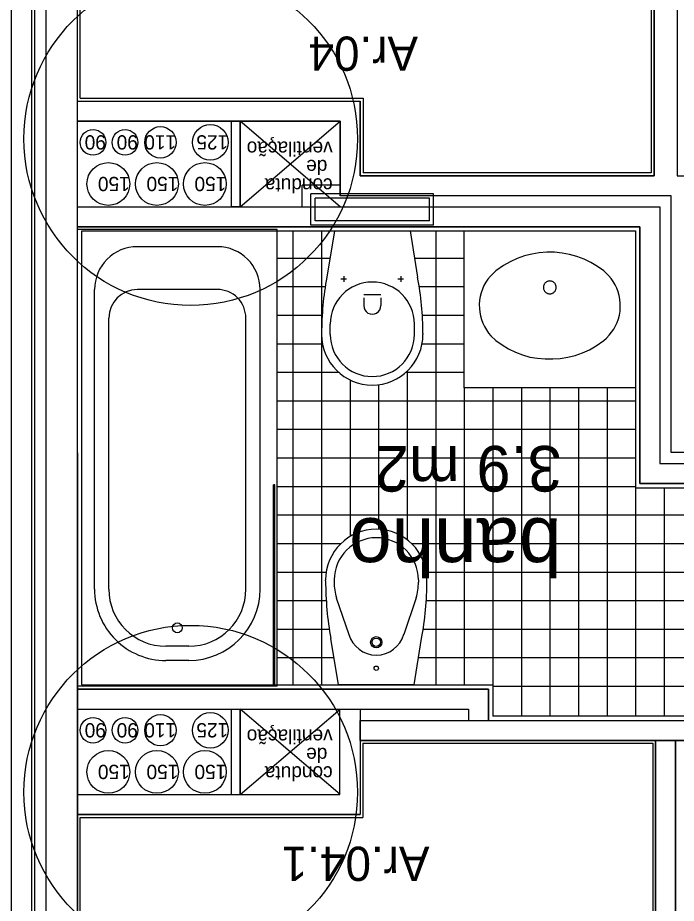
# Model space of a CAD drawing. Extents: x 1278 to 1356, y -253.7 to -224.
# Drawn here: x 1334.624 to 1336.931, y -240.985 to -237.882 of the extents above; entities that cross this region are included whole.
import ezdxf

# ---------------------------------------------------------------- set-up
doc = ezdxf.new("R2010")
doc.units = 0
for name, color, linetype in [('Level 1', 7, 'Continuous'), ('Level 10', 7, 'Continuous'), ('Level 11', 7, 'Continuous'), ('Level 2', 7, 'Continuous'), ('Level 36', 7, 'Continuous'), ('Level 40', 7, 'Continuous'), ('Level 41', 7, 'Continuous'), ('Level 60', 7, 'Continuous'), ('Level 65', 7, 'Continuous'), ('Level 66', 7, 'Continuous'), ('Level 67', 7, 'Continuous'), ('Level 69', 7, 'Continuous'), ('Level 70', 7, 'Continuous')]:
    doc.layers.add(name, color=color, linetype=linetype)

msp = doc.modelspace()

# ---------------------------------------------------------------- linework, layer by layer
at = {"layer": 'Level 1'}
for p, q in [((1334.8333, -246.584), (1334.8332, -232.2657)), ((1336.8533, -236.6557), (1336.8533, -238.4357)), ((1334.6725, -236.7713), (1334.6725, -242.1713)), ((1334.7233, -242.1713), (1334.7233, -236.7713)), ((1334.8333, -238.174), (1335.8241, -238.174)), ((1334.8333, -238.244), (1335.7533, -238.244)), ((1335.3733, -238.544), (1335.3733, -238.244)), ((1335.4033, -238.544), (1335.4033, -238.244)), ((1336.8533, -238.4357), (1335.8241, -238.4357)), ((1335.7533, -238.469), (1335.6209, -238.469)), ((1335.7533, -238.499), (1335.6509, -238.499)), ((1336.9133, -238.5057), (1335.7533, -238.5057)), ((1336.9133, -239.4057), (1336.9133, -238.5057)), ((1334.8333, -238.544), (1336.8733, -238.544)), ((1336.8733, -238.544), (1336.8733, -239.444)), ((1334.8333, -238.614), (1336.8033, -238.614)), ((1336.8033, -238.614), (1336.8033, -239.514)), ((1337.9133, -239.4057), (1336.9133, -239.4057)), ((1336.8733, -239.444), (1337.8733, -239.444)), ((1336.8033, -239.514), (1337.8033, -239.514)), ((1334.8333, -240.234), (1336.2733, -240.234)), ((1336.2733, -240.234), (1336.2733, -240.344)), ((1334.8333, -240.304), (1335.7525, -240.304)), ((1335.3733, -240.604), (1335.3733, -240.304)), ((1335.4033, -240.604), (1335.4033, -240.304)), ((1335.8233, -240.304), (1336.2033, -240.304)), ((1336.2033, -240.304), (1336.2033, -240.344)), ((1335.8233, -240.414), (1336.8583, -240.414)), ((1336.8583, -240.414), (1336.8583, -242.194)), ((1336.9283, -242.194), (1336.9283, -240.414)), ((1336.9283, -240.414), (1337.0383, -240.414)), ((1334.8333, -240.604), (1335.7525, -240.604)), ((1334.8325, -240.674), (1335.8233, -240.674))]:
    msp.add_line(p, q, dxfattribs=at)
for points in [[(1335.8241, -238.4357), (1335.8241, -238.174)], [(1335.7533, -238.244), (1335.7533, -238.5057)], [(1335.8233, -240.304), (1335.8233, -240.344)], [(1335.8233, -240.414), (1335.8233, -240.674)]]:
    msp.add_lwpolyline(points, dxfattribs=at)
at = {"layer": 'Level 10'}
for p, q in [((1335.5883, -238.629), (1335.5883, -240.219)), ((1335.6883, -238.629), (1335.6883, -240.219)), ((1336.0883, -238.629), (1336.0883, -240.219)), ((1335.5333, -238.724), (1335.718, -238.724)), ((1336.0139, -238.724), (1336.1883, -238.724)), ((1335.5333, -238.824), (1335.7013, -238.824)), ((1336.0306, -238.824), (1336.1883, -238.824)), ((1335.5333, -238.924), (1335.6904, -238.924)), ((1336.0415, -238.924), (1336.1883, -238.924)), ((1335.5333, -239.024), (1335.6915, -239.024)), ((1336.0405, -239.024), (1336.1883, -239.024)), ((1335.5333, -239.124), (1335.7479, -239.124)), ((1335.9841, -239.124), (1336.1883, -239.124)), ((1335.9883, -239.1201), (1335.9883, -239.7109)), ((1335.7883, -239.1511), (1335.7883, -239.6995)), ((1335.8883, -239.1676), (1335.8883, -239.6742)), ((1336.1883, -239.179), (1336.1883, -240.219)), ((1336.2883, -239.179), (1336.2883, -240.219)), ((1336.3883, -239.179), (1336.3883, -240.329)), ((1336.4883, -239.179), (1336.4883, -240.329)), ((1336.5883, -239.179), (1336.5883, -240.329)), ((1336.6883, -239.179), (1336.6883, -240.329)), ((1335.5333, -239.224), (1336.7883, -239.224)), ((1335.5333, -239.324), (1336.7883, -239.324)), ((1335.5333, -239.424), (1336.7883, -239.424)), ((1335.5333, -239.524), (1336.7883, -239.524)), ((1336.7883, -239.529), (1336.7883, -240.329)), ((1336.8883, -239.529), (1336.8883, -240.329)), ((1335.5333, -239.624), (1337.7883, -239.624)), ((1335.5333, -239.724), (1335.7565, -239.724)), ((1336.0034, -239.724), (1337.7883, -239.724)), ((1335.5333, -239.824), (1335.7027, -239.824)), ((1336.057, -239.824), (1337.6983, -239.824)), ((1335.5333, -239.924), (1335.7046, -239.924)), ((1336.0553, -239.924), (1337.6983, -239.924)), ((1335.5333, -240.024), (1335.7154, -240.024)), ((1336.0445, -240.024), (1337.6983, -240.024)), ((1335.5333, -240.124), (1335.732, -240.124)), ((1336.0279, -240.124), (1337.6983, -240.124)), ((1336.2883, -240.224), (1337.6983, -240.224))]:
    msp.add_line(p, q, dxfattribs=at)
at = {"layer": 'Level 11'}
for p, q in [((1335.6509, -238.609), (1335.6509, -238.499)), ((1336.0809, -238.499), (1335.6509, -238.499)), ((1336.0659, -238.514), (1335.6659, -238.514)), ((1335.6659, -238.594), (1335.6659, -238.514)), ((1336.0659, -238.594), (1336.0659, -238.514)), ((1336.0809, -238.609), (1336.0809, -238.499)), ((1336.0809, -238.609), (1335.6509, -238.609)), ((1336.0659, -238.594), (1335.6659, -238.594)), ((1335.5333, -238.624), (1334.8333, -238.624)), ((1334.8333, -240.224), (1334.8333, -238.624)), ((1334.8333, -240.229), (1334.8333, -238.629)), ((1335.5333, -240.224), (1335.5333, -238.624)), ((1335.7336, -238.629), (1335.707, -238.791)), ((1335.7336, -238.629), (1335.9983, -238.629)), ((1335.9983, -238.629), (1336.0249, -238.791)), ((1335.3233, -238.684), (1335.0433, -238.684)), ((1336.4511, -238.7055), (1336.4246, -238.7099)), ((1336.4777, -238.7034), (1336.4511, -238.7055)), ((1336.5044, -238.7037), (1336.4777, -238.7034)), ((1336.5309, -238.7063), (1336.5044, -238.7037)), ((1336.5571, -238.7113), (1336.5309, -238.7063)), ((1336.3493, -238.7367), (1336.3261, -238.75)), ((1336.3736, -238.7256), (1336.3493, -238.7367)), ((1336.3988, -238.7166), (1336.3736, -238.7256)), ((1336.4246, -238.7099), (1336.3988, -238.7166)), ((1336.583, -238.7185), (1336.5571, -238.7113)), ((1336.608, -238.728), (1336.583, -238.7185)), ((1336.632, -238.7397), (1336.608, -238.728)), ((1336.299, -238.7691), (1336.289, -238.7779)), ((1336.3261, -238.75), (1336.299, -238.7691)), ((1336.655, -238.7534), (1336.632, -238.7397)), ((1336.6767, -238.7691), (1336.655, -238.7534)), ((1336.6939, -238.7851), (1336.6767, -238.7691)), ((1335.7559, -238.7972), (1335.7759, -238.7972)), ((1335.7659, -238.7872), (1335.7659, -238.8072)), ((1335.9559, -238.7972), (1335.9759, -238.7972)), ((1335.9659, -238.7872), (1335.9659, -238.8072)), ((1336.2713, -238.7978), (1336.2638, -238.8089)), ((1336.2797, -238.7874), (1336.2713, -238.7978)), ((1336.289, -238.7779), (1336.2797, -238.7874)), ((1336.7025, -238.7953), (1336.6939, -238.7851)), ((1336.7102, -238.8062), (1336.7025, -238.7953)), ((1336.2573, -238.8206), (1336.2518, -238.8328)), ((1336.2638, -238.8089), (1336.2573, -238.8206)), ((1336.4656, -238.8248), (1336.4655, -238.8267)), ((1336.4655, -238.8267), (1336.4656, -238.8287)), ((1336.4659, -238.8228), (1336.4656, -238.8248)), ((1336.4656, -238.8287), (1336.4659, -238.8307)), ((1336.4663, -238.8209), (1336.4659, -238.8228)), ((1336.4659, -238.8307), (1336.4663, -238.8326)), ((1336.4669, -238.819), (1336.4663, -238.8209)), ((1336.4676, -238.8172), (1336.4669, -238.819)), ((1336.4685, -238.8155), (1336.4676, -238.8172)), ((1336.4696, -238.8138), (1336.4685, -238.8155)), ((1336.4708, -238.8122), (1336.4696, -238.8138)), ((1336.4721, -238.8108), (1336.4708, -238.8122)), ((1336.4735, -238.8095), (1336.4721, -238.8108)), ((1336.4751, -238.8083), (1336.4735, -238.8095)), ((1336.4767, -238.8072), (1336.4751, -238.8083)), ((1336.4784, -238.8063), (1336.4767, -238.8072)), ((1336.4802, -238.8055), (1336.4784, -238.8063)), ((1336.4821, -238.8049), (1336.4802, -238.8055)), ((1336.484, -238.8045), (1336.4821, -238.8049)), ((1336.4859, -238.8043), (1336.484, -238.8045)), ((1336.4878, -238.8042), (1336.4859, -238.8043)), ((1336.4898, -238.8043), (1336.4878, -238.8042)), ((1336.4917, -238.8045), (1336.4898, -238.8043)), ((1336.4936, -238.8049), (1336.4917, -238.8045)), ((1336.4955, -238.8055), (1336.4936, -238.8049)), ((1336.4973, -238.8063), (1336.4955, -238.8055)), ((1336.499, -238.8072), (1336.4973, -238.8063)), ((1336.5006, -238.8083), (1336.499, -238.8072)), ((1336.5022, -238.8095), (1336.5006, -238.8083)), ((1336.5036, -238.8108), (1336.5022, -238.8095)), ((1336.5049, -238.8122), (1336.5036, -238.8108)), ((1336.5061, -238.8138), (1336.5049, -238.8122)), ((1336.5072, -238.8155), (1336.5061, -238.8138)), ((1336.5081, -238.8172), (1336.5072, -238.8155)), ((1336.5088, -238.819), (1336.5081, -238.8172)), ((1336.5094, -238.8209), (1336.5088, -238.819)), ((1336.5098, -238.8228), (1336.5094, -238.8209)), ((1336.5094, -238.8326), (1336.5098, -238.8307)), ((1336.5101, -238.8248), (1336.5098, -238.8228)), ((1336.5098, -238.8307), (1336.5101, -238.8287)), ((1336.5102, -238.8267), (1336.5101, -238.8248)), ((1336.5101, -238.8287), (1336.5102, -238.8267)), ((1336.717, -238.8177), (1336.7102, -238.8062)), ((1336.7227, -238.8298), (1336.717, -238.8177)), ((1336.7274, -238.8424), (1336.7227, -238.8298)), ((1334.8933, -239.884), (1334.8933, -238.834)), ((1335.3233, -238.834), (1335.0433, -238.834)), ((1335.4733, -239.884), (1335.4733, -238.834)), ((1335.8359, -238.8512), (1335.8959, -238.8512)), ((1336.2441, -238.8584), (1336.2419, -238.8716)), ((1336.2474, -238.8454), (1336.2441, -238.8584)), ((1336.2518, -238.8328), (1336.2474, -238.8454)), ((1336.4663, -238.8326), (1336.4669, -238.8345)), ((1336.4669, -238.8345), (1336.4676, -238.8363)), ((1336.4676, -238.8363), (1336.4685, -238.838)), ((1336.4685, -238.838), (1336.4696, -238.8397)), ((1336.4696, -238.8397), (1336.4708, -238.8412)), ((1336.4708, -238.8412), (1336.4721, -238.8427)), ((1336.4721, -238.8427), (1336.4735, -238.844)), ((1336.4735, -238.844), (1336.4751, -238.8452)), ((1336.4751, -238.8452), (1336.4767, -238.8463)), ((1336.4767, -238.8463), (1336.4784, -238.8472)), ((1336.4784, -238.8472), (1336.4802, -238.8479)), ((1336.4802, -238.8479), (1336.4821, -238.8485)), ((1336.4821, -238.8485), (1336.484, -238.849)), ((1336.484, -238.849), (1336.4859, -238.8492)), ((1336.4859, -238.8492), (1336.4878, -238.8493)), ((1336.4878, -238.8493), (1336.4898, -238.8492)), ((1336.4898, -238.8492), (1336.4917, -238.849)), ((1336.4917, -238.849), (1336.4936, -238.8485)), ((1336.4936, -238.8485), (1336.4955, -238.8479)), ((1336.4955, -238.8479), (1336.4973, -238.8472)), ((1336.4973, -238.8472), (1336.499, -238.8463)), ((1336.499, -238.8463), (1336.5006, -238.8452)), ((1336.5006, -238.8452), (1336.5022, -238.844)), ((1336.5022, -238.844), (1336.5036, -238.8427)), ((1336.5036, -238.8427), (1336.5049, -238.8412)), ((1336.5049, -238.8412), (1336.5061, -238.8397)), ((1336.5061, -238.8397), (1336.5072, -238.838)), ((1336.5072, -238.838), (1336.5081, -238.8363)), ((1336.5081, -238.8363), (1336.5088, -238.8345)), ((1336.5088, -238.8345), (1336.5094, -238.8326)), ((1336.7309, -238.8553), (1336.7274, -238.8424)), ((1336.7334, -238.8685), (1336.7309, -238.8553)), ((1335.8359, -238.8635), (1335.8359, -238.8907)), ((1335.8959, -238.8635), (1335.8959, -238.8907)), ((1336.2419, -238.8716), (1336.2409, -238.8863)), ((1336.2409, -238.8863), (1336.241, -238.9001)), ((1336.7347, -238.8831), (1336.7334, -238.8685)), ((1336.7348, -238.8969), (1336.7347, -238.8831)), ((1336.241, -238.9001), (1336.2423, -238.9135)), ((1336.2423, -238.9135), (1336.2448, -238.9267)), ((1336.7283, -238.9365), (1336.7316, -238.9235)), ((1336.7316, -238.9235), (1336.7338, -238.9103)), ((1336.7338, -238.9103), (1336.7348, -238.8969)), ((1334.9433, -239.884), (1334.9433, -238.934)), ((1335.4233, -239.884), (1335.4233, -238.934)), ((1335.7184, -238.9915), (1335.7184, -238.9554)), ((1336.0134, -238.9915), (1336.0134, -238.9554)), ((1336.2448, -238.9267), (1336.2483, -238.9396)), ((1336.2483, -238.9396), (1336.253, -238.9521)), ((1336.253, -238.9521), (1336.2587, -238.9642)), ((1336.7184, -238.9614), (1336.7239, -238.9492)), ((1336.7239, -238.9492), (1336.7283, -238.9365)), ((1336.2587, -238.9642), (1336.2655, -238.9758)), ((1336.2655, -238.9758), (1336.2732, -238.9867)), ((1336.2732, -238.9867), (1336.2818, -238.9969)), ((1336.696, -238.9945), (1336.7044, -238.9841)), ((1336.7044, -238.9841), (1336.7119, -238.9731)), ((1336.7119, -238.9731), (1336.7184, -238.9614)), ((1335.6885, -238.9881), (1335.6884, -238.9918)), ((1336.0434, -238.9881), (1336.0434, -238.9918)), ((1336.2818, -238.9969), (1336.299, -239.0128)), ((1336.299, -239.0128), (1336.3207, -239.0285)), ((1336.6496, -239.032), (1336.6767, -239.0128)), ((1336.6767, -239.0128), (1336.6867, -239.0041)), ((1336.6867, -239.0041), (1336.696, -238.9945)), ((1336.3207, -239.0285), (1336.3437, -239.0422)), ((1336.3437, -239.0422), (1336.3677, -239.0539)), ((1336.6021, -239.0564), (1336.6264, -239.0452)), ((1336.6264, -239.0452), (1336.6496, -239.032)), ((1336.3677, -239.0539), (1336.3927, -239.0634)), ((1336.3927, -239.0634), (1336.4184, -239.0706)), ((1336.4184, -239.0706), (1336.4448, -239.0746)), ((1336.4448, -239.0746), (1336.4713, -239.0772)), ((1336.4713, -239.0772), (1336.498, -239.0775)), ((1336.498, -239.0775), (1336.5246, -239.0754)), ((1336.5246, -239.0754), (1336.5509, -239.071)), ((1336.5509, -239.071), (1336.5769, -239.0653)), ((1336.5769, -239.0653), (1336.6021, -239.0564)), ((1335.7025, -239.8548), (1335.7025, -239.8512)), ((1335.7325, -239.8515), (1335.7325, -239.8596)), ((1336.0275, -239.8515), (1336.0275, -239.8596)), ((1336.0575, -239.8548), (1336.0575, -239.8512)), ((1335.7401, -239.9145), (1335.7838, -240.0424)), ((1336.0198, -239.9145), (1335.9761, -240.0424)), ((1335.7476, -240.219), (1335.721, -240.0569)), ((1336.0123, -240.219), (1336.0389, -240.0569)), ((1335.2233, -240.084), (1335.1433, -240.084)), ((1335.2233, -240.134), (1335.1433, -240.134)), ((1335.5333, -240.224), (1334.8333, -240.224)), ((1336.0123, -240.219), (1335.7476, -240.219))]:
    msp.add_line(p, q, dxfattribs=at)
for centre, radius in [((1335.1833, -240.0195), 0.0173), ((1335.88, -240.0701), 0.02), ((1335.88, -240.0701), 0.0146), ((1335.88, -240.161), 0.00766)]:
    msp.add_circle(centre, radius, dxfattribs=at)
for centre, radius, start, end in [((1335.0433, -238.834), 0.15, 89.9999, 180.0002), ((1335.3233, -238.834), 0.15, 360, 90), ((1335.866, -238.9554), 0.1475, 0.0002, 179.9999), ((1335.0433, -238.934), 0.1, 90.0001, 179.9999), ((1335.3233, -238.934), 0.1, 360, 90.0001), ((1335.866, -238.8905), 0.03, 179.9995, 0.0013), ((1335.866, -238.9915), 0.1775, 180.0002, 359.9999), ((1335.866, -238.9915), 0.1475, 180.0002, 359.9999), ((1335.88, -239.8515), 0.1775, 0.0002, 179.9999), ((1335.88, -239.8515), 0.1475, 0.0002, 179.9999), ((1335.1433, -239.884), 0.25, 180, 270.0001), ((1335.1433, -239.884), 0.2, 180, 270), ((1335.2233, -239.884), 0.25, 269.9999, 359.9999), ((1335.2233, -239.884), 0.2, 270, 0), ((1335.9325, -239.8596), 0.2, 180.0017, 195.9319), ((1335.8275, -239.8596), 0.2, 344.0693, 0.0006), ((1335.88, -240.015), 0.1, 195.9317, 344.1953)]:
    msp.add_arc(centre, radius, start, end, dxfattribs=at)
for centre, major_axis, ratio, start_param, end_param in [((1337.0885, -238.9881), (-1.4, 0), 0.867931, 6.120269, 6.283188), ((1334.6435, -238.9881), (1.4, 0), 0.867931, 6.283184, 6.446103), ((1337.1025, -239.8549), (-1.4, 0), 0.88995, 6.283183, 6.446102), ((1334.6575, -239.8549), (1.4, 0), 0.88995, 6.120269, 6.283187)]:
    msp.add_ellipse(centre, major_axis=major_axis, ratio=ratio, start_param=start_param, end_param=end_param, dxfattribs=at)
at = {"layer": 'Level 2'}
for p, q in [((1336.1883, -239.179), (1336.1883, -238.629)), ((1336.7883, -238.629), (1336.7883, -239.179)), ((1336.7883, -239.179), (1336.1883, -239.179))]:
    msp.add_line(p, q, dxfattribs=at)
at = {"layer": 'Level 36'}
for p, q in [((1335.5253, -239.519), (1335.5203, -239.519)), ((1335.5203, -240.219), (1335.5203, -239.519)), ((1335.5253, -240.219), (1335.5253, -239.519))]:
    msp.add_line(p, q, dxfattribs=at)
at = {"layer": 'Level 41'}
for p, q in [((1335.7533, -238.544), (1335.4033, -238.244)), ((1335.4033, -238.544), (1335.7533, -238.244)), ((1335.7533, -240.604), (1335.4033, -240.304)), ((1335.4033, -240.604), (1335.7533, -240.304))]:
    msp.add_line(p, q, dxfattribs=at)
for centre, radius in [((1335.1241, -238.3185), 0.055), ((1335.2989, -238.3185), 0.0625), ((1334.8881, -238.3185), 0.045), ((1335.0001, -238.3185), 0.045), ((1334.9416, -238.4644), 0.075), ((1335.1118, -238.4644), 0.075), ((1335.2798, -238.4644), 0.075), ((1335.2989, -240.3785), 0.0625), ((1334.8881, -240.3785), 0.045), ((1335.0001, -240.3785), 0.045), ((1335.1241, -240.3785), 0.055), ((1334.9416, -240.5244), 0.075), ((1335.1118, -240.5244), 0.075), ((1335.2798, -240.5244), 0.075)]:
    msp.add_circle(centre, radius, dxfattribs=at)
at = {"layer": 'Level 65'}
for p, q in [((1336.8433, -236.6557), (1336.8433, -238.4257)), ((1334.8433, -238.164), (1335.8341, -238.164)), ((1335.8341, -238.164), (1335.8341, -238.4257)), ((1336.8433, -238.4257), (1335.8341, -238.4257)), ((1334.8483, -240.219), (1334.8483, -238.629)), ((1334.8483, -238.629), (1336.7883, -238.629)), ((1336.7883, -238.629), (1336.7883, -239.529)), ((1336.7883, -239.529), (1337.7883, -239.529)), ((1334.8483, -240.219), (1336.2883, -240.219)), ((1336.2883, -240.219), (1336.2883, -240.329)), ((1337.0383, -240.329), (1336.2883, -240.329)), ((1335.8333, -240.424), (1336.8483, -240.424)), ((1336.8483, -240.424), (1336.8483, -242.194)), ((1334.8433, -242.029), (1334.8433, -240.684)), ((1334.8433, -240.684), (1335.8333, -240.684))]:
    msp.add_line(p, q, dxfattribs=at)
for points in [[(1334.8433, -238.164), (1334.8433, -236.8257)], [(1335.8333, -240.424), (1335.8333, -240.684)]]:
    msp.add_lwpolyline(points, dxfattribs=at)
at = {"layer": 'Level 66'}
for p, q in [((1335.6209, -238.544), (1335.6209, -238.469)), ((1335.6509, -238.544), (1335.6509, -238.499)), ((1335.6509, -238.544), (1335.6509, -238.5057)), ((1335.7525, -240.604), (1335.7525, -240.304)), ((1335.8233, -240.344), (1336.2033, -240.344)), ((1336.2733, -240.344), (1337.0383, -240.344))]:
    msp.add_line(p, q, dxfattribs=at)
at = {"layer": 'Level 67'}
for points in [[(1340.0033, -240.234), (1340.0033, -240.304), (1337.9133, -240.304), (1337.9133, -239.4057), (1336.9133, -239.4057), (1336.9133, -238.5057), (1335.7533, -238.5057), (1335.7533, -238.244), (1334.8332, -238.244), (1334.8333, -238.174), (1335.8241, -238.174), (1335.8241, -238.4357), (1336.8533, -238.4357), (1336.8533, -236.6557), (1336.9333, -236.6557), (1336.9333, -238.4357), (1337.022, -238.4357), (1337.0183, -238.4357), (1337.0183, -238.5057), (1336.9833, -238.5057), (1336.9833, -239.3357), (1337.9833, -239.3357), (1337.9833, -240.234), (1340.0033, -240.234)], [(1334.6725, -242.1713), (1334.6025, -242.1713), (1334.6025, -242.104), (1332.5275, -242.104), (1332.5275, -242.194), (1332.4575, -242.194), (1332.4575, -242.034), (1334.6025, -242.034), (1334.6025, -236.7713), (1334.6725, -236.7713)], [(1335.4333, -242.039), (1335.4333, -242.109), (1334.8333, -242.109), (1334.8333, -242.1713), (1334.7233, -242.1713), (1334.7233, -236.7713), (1334.8325, -236.7713), (1334.8333, -242.039)], [(1335.4033, -238.244), (1335.4033, -238.544), (1335.3733, -238.544), (1335.3733, -238.244)], [(1340.0033, -240.414), (1337.7683, -240.414), (1337.7683, -240.339), (1337.8033, -240.339), (1337.8033, -239.514), (1336.8033, -239.514), (1336.8033, -238.614), (1334.8333, -238.614), (1334.8333, -238.544), (1336.8733, -238.544), (1336.8733, -239.444), (1337.8733, -239.444), (1337.8733, -240.344), (1340.0033, -240.344)], [(1336.2733, -240.344), (1336.2733, -240.234), (1334.8333, -240.234), (1334.8333, -240.304), (1336.2033, -240.304), (1336.2033, -240.344)], [(1335.8233, -240.304), (1335.8233, -240.674), (1334.8333, -240.674), (1334.8333, -240.604), (1335.3733, -240.604), (1335.3733, -240.304), (1335.4033, -240.304), (1335.4033, -240.604), (1335.7525, -240.604), (1335.7525, -240.304)], [(1337.0383, -240.344), (1337.0383, -240.414), (1335.8233, -240.414), (1335.8233, -240.344)], [(1336.9283, -240.414), (1336.9283, -242.194), (1336.8583, -242.194), (1336.8583, -240.414)]]:
    msp.add_lwpolyline(points, close=True, dxfattribs=at)
at = {"layer": 'Level 69'}
for centre in [(1335.2301, -238.3059), (1335.2301, -240.5951)]:
    msp.add_circle(centre, 0.5842, dxfattribs=at)
at = {"layer": 'Level 70'}
msp.add_line((1334.684, -250.7923), (1334.684, -229.6198), dxfattribs=at)

# ---------------------------------------------------------------- texts
at = {"layer": 'Level 40'}
for s, p in [('Ar.04', (1336.0262, -237.9477)), ('Ar.04.1', (1336.0665, -240.7863))]:
    msp.add_text(s, height=0.12, rotation=180, dxfattribs=at).set_placement(p)
at = {"layer": 'Level 41'}
for s, p in [('90', (1334.9331, -238.2935)), ('90', (1335.0451, -238.2935)), ('110', (1335.1791, -238.2935)), ('125', (1335.3614, -238.2935)), ('ventilação ', (1335.7273, -238.3155)), (' de ', (1335.7273, -238.3799)), ('150', (1335.0166, -238.4394)), ('150', (1335.1868, -238.4394)), ('150', (1335.3548, -238.4394)), ('conduta', (1335.7273, -238.4444)), ('90', (1334.9331, -240.3535)), ('90', (1335.0451, -240.3535)), ('110', (1335.1791, -240.3535)), ('125', (1335.3614, -240.3535)), ('ventilação ', (1335.7273, -240.3755)), (' de ', (1335.7273, -240.4399)), ('150', (1335.0166, -240.4994)), ('150', (1335.1868, -240.4994)), ('150', (1335.3548, -240.4994)), ('conduta', (1335.7273, -240.5044))]:
    msp.add_text(s, height=0.05, rotation=180, dxfattribs=at).set_placement(p)
at = {"layer": 'Level 60'}
for s, height, p in [('3.9 m2', 0.16, (1336.5292, -239.3821)), ('banho', 0.2, (1336.529, -239.6356))]:
    msp.add_text(s, height=height, rotation=180, dxfattribs=at).set_placement(p)

doc.saveas('drawing.dxf')
